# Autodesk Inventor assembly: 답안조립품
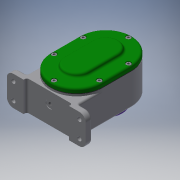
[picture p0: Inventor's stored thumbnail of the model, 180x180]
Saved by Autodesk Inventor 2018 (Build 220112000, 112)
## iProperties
Created: 2021-05
Part Number: 답안조립품
Material: 일반
Document SubType Name: Assembly
Designer: Admin
Author: Admin
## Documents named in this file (19)
- C:\Users\Admin\Desktop\710509V1014\답안조립품.iam
- C:\Users\Admin\Desktop\710509V1014\본체.ipt
- C:\Users\Admin\Desktop\710509V1014\커버 B.ipt
- C:\Users\Admin\Desktop\710509V1014\오일 실 12 22 7.ipt
- C:\Users\Admin\Desktop\710509V1014\축 A.ipt
- C:\Users\Admin\Desktop\710509V1014\칼라.ipt
- C:\Users\Admin\Desktop\710509V1014\베어링 6001.ipt
- 베어링 6001.ipt
- C:\Users\Admin\Desktop\710509V1014\키 5 x 5 x 12.ipt
- C:\Users\Admin\Desktop\710509V1014\스퍼기어 A.ipt
- C:\Users\Admin\Desktop\710509V1014\개스킷 B.ipt
- C:\Users\Admin\Desktop\710509V1014\축 B.ipt
- C:\Users\Admin\Desktop\710509V1014\키 4 x 4 x 12.ipt
- C:\Users\Admin\Desktop\710509V1014\베어링 6002.ipt
- 베어링 6002.ipt
- C:\Users\Admin\Desktop\710509V1014\스퍼기어 B.ipt
- C:\Users\Admin\Desktop\710509V1014\커버 A.ipt
- C:\Users\Admin\Desktop\710509V1014\개스킷 A.ipt
- C:\Users\Admin\Desktop\710509V1014\볼트 M4.ipt
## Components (2 placed, 2 different names)
1. 개스킷 B:1
2. 개스킷 A:1
